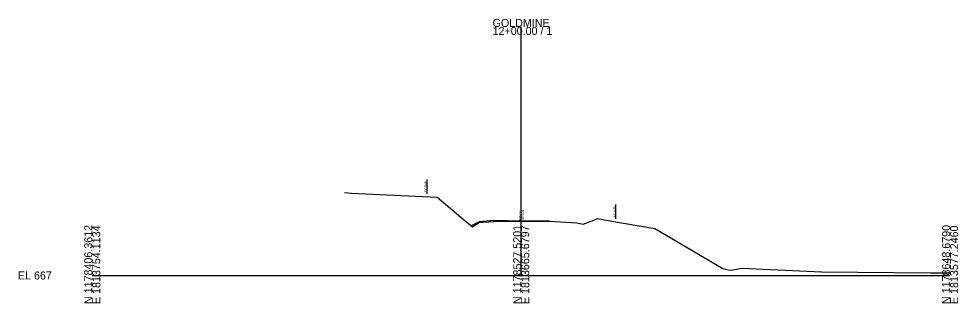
# Model space of a CAD drawing. Extents: x -26 to 1603, y -10 to 1590.
# Drawn here: x 1274.3 to 1602.8, y 1490.3 to 1589.7 of the extents above; entities that cross this region are included whole.
import ezdxf

# ---------------------------------------------------------------- set-up
doc = ezdxf.new("R2010")
doc.units = 0
for name, color, linetype in [('Default', 7, 'Continuous'), ('RD_EX_RW', 7, 'Continuous'), ('RD_GPK_XS_Cell', 7, 'Continuous'), ('RD_XS_ExGround', 7, 'Continuous'), ('RD_XS_Misc_Line', 7, 'Continuous'), ('RD_XS_TX_Elev_EX', 7, 'Continuous')]:
    doc.layers.add(name, color=color, linetype=linetype)

msp = doc.modelspace()

# ---------------------------------------------------------------- linework, layer by layer
at = {"layer": 'Default'}
for q in [(1440.49, 1518.87), (1459.96, 1519.04)]:
    msp.add_line((1450, 1519.03), q, dxfattribs=at)
at = {"layer": 'RD_EX_RW'}
for p, q in [((1417, 1533.51), (1417, 1528.51)), ((1483, 1524.79), (1483, 1519.79))]:
    msp.add_line(p, q, dxfattribs=at)
at = {"layer": 'RD_GPK_XS_Cell'}
for p, q in [((1450, 1500), (1450, 1586.89)), ((1300, 1500), (1450, 1500)), ((1450, 1500), (1600, 1500))]:
    msp.add_line(p, q, dxfattribs=at)
at = {"layer": 'RD_XS_ExGround'}
msp.add_lwpolyline([(1388.19, 1528.96), (1390.69, 1528.8), (1420.57, 1527.34), (1428.85, 1520.44), (1432.96, 1517.03), (1434.86, 1518.3), (1435.33, 1518.61), (1436.7, 1518.68), (1440.49, 1518.87), (1449.07, 1519.01), (1450, 1519.03), (1450.73, 1519.04), (1457.01, 1519.04), (1459.96, 1519.04), (1469.42, 1518.46), (1470.09, 1518.31), (1471.64, 1517.89), (1475.43, 1519.37), (1476.66, 1519.87), (1481.01, 1519.14), (1496.71, 1516.42), (1502.11, 1513.3), (1520.52, 1502.43), (1522.4, 1502.03), (1523.37, 1501.83), (1524.12, 1501.97), (1527.02, 1502.51), (1537.18, 1502.08), (1555.05, 1501.33), (1593.2, 1500.91), (1600, 1500.87)], dxfattribs=at)
at = {"layer": 'RD_XS_Misc_Line'}
for points in [[(1434.86, 1518.3), (1435.33, 1518.61), (1436.7, 1518.68), (1440.49, 1518.87), (1440.49, 1519.19), (1435.32, 1518.76), (1432.55, 1517.37), (1432.96, 1517.03)], [(1450, 1519.03), (1440.49, 1519.19), (1440.49, 1518.87), (1449.07, 1519.01)], [(1457.01, 1519.04), (1459.96, 1519.04), (1459.96, 1519.03), (1450, 1519.03), (1450.73, 1519.04)]]:
    msp.add_lwpolyline(points, close=True, dxfattribs=at)

# ---------------------------------------------------------------- texts
at = {"layer": 'Default'}
msp.add_text('686.03', height=0.8, rotation=90, dxfattribs=at).set_placement((1451.01, 1519.56))
at = {"layer": 'RD_EX_RW'}
for p in [(1416.94, 1529.04), (1482.94, 1520.32)]:
    msp.add_text('EX. R/W', height=0.75, rotation=90, dxfattribs=at).set_placement(p)
at = {"layer": 'RD_GPK_XS_Cell'}
for s, p in [('GOLDMINE', (1440, 1586.89)), ('12+00.00 / 1', (1440, 1584.09)), ('EL 667', (1274, 1498.6))]:
    msp.add_text(s, height=2.8, dxfattribs=at).set_placement(p)
for s, p in [('N 1178406.3612', (1300, 1490)), ('E 1813754.1134', (1302.8, 1490)), ('N 1178527.5201', (1450, 1490)), ('E 1813665.6797', (1452.8, 1490)), ('N 1178648.6790', (1600, 1490)), ('E 1813577.2460', (1602.8, 1490))]:
    msp.add_text(s, height=2.8, rotation=90, dxfattribs=at).set_placement(p)
at = {"layer": 'RD_XS_TX_Elev_EX'}
msp.add_text('686.03', height=0.75, rotation=90, dxfattribs=at).set_placement((1449.95, 1519.22))

doc.saveas('drawing.dxf')
